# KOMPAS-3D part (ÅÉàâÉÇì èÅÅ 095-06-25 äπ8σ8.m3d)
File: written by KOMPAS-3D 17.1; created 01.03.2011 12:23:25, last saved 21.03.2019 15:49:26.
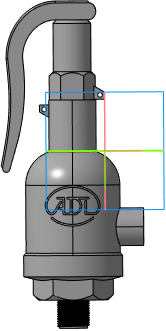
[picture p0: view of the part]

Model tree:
1. Операция без истории:1

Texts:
  Viktor2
